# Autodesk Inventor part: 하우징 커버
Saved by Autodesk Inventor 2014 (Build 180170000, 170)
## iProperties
Created: 2026-01
Part Number: 하우징 커버
Material: 일반
Document SubType Name: Modeling
Designer: dg
Density: 1 g/cm^3
Appearance: 기본값
Author: dg
Author: jhkim
Creation Date: 2026-01-09
Sending System: Autodesk Inventor 2026
Preprocessor: ST-DEVELOPER v20.1
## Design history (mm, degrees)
node "하우징 커버1"
node "솔리드1"
node "기준1"
